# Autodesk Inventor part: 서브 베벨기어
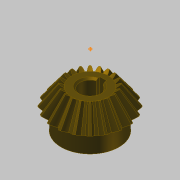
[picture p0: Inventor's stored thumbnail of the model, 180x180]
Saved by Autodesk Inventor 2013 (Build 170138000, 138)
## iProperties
Created: 2014-10
Part Number: 서브 베벨기어
Material: 강철, 탄소
Document SubType Name: Modeling
Designer: KYOUNG IL JANG
Categories: <?xml version="1.0" encoding="UTF-16"?> <MemberInstance><Categories><FamilyTemplate><FamilyTemplateParameter ValueType="xs:double" Id="1" ObjectReferenceKey="da
Mass: 134.866 g
Surface Area: 63.6518 cm^2
Volume: 17.1585 cm^3
Density: 7.86 g/cm^3
CustomPartVersion: 1
Revision Number: 1
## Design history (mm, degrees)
node "맨 위 점"
node "메쉬 평면2"
sketch "톱니 본체 스케치"
  geometry: L1 (0, 0)-(18.003, -31.331); L2 (18.003, -31.331)-(21.664, -28.891); L3 (21.664, -28.891)-(0, 0); L4 (20, -30)-(0, 0); L5 (10.813, -18.818)-(13.012, -17.352); L6 (18.003, -31.331)-(10.813, -18.818); L7 (21.664, -28.891)-(13.012, -17.352); L8 (0, -39.387)-(0, 6.564) reference; L9 (0, -30)-(21.664, -30)
  constraints: 16 end point, 4 point on line, 3 perpendicular, 2 collinear, 1 horizontal alignment, 1 vertical alignment
  dimensions: "d0" = 40 diameter of L4.start L8 (= da_de); "d1" = 36.00616 diameter of L1.end L8 (= da_dfe); "d2" = 43.3282 diameter of L2.end L8 (= da_dae); "d3" = 14.4 distance between parallel lines of L2 L5 (= da_b); "d4" = 28.8906 vertical distance of L2.end L1.start (= da_ve)
revolve "톱니 본체" sketch "톱니 본체 스케치" stored, may be unused: angle "d5" = 90 deg
node "시작점"
node "톱니 평면"
sketch "시작 스케치"
  geometry: L1 (0, -23.505)-(0, 10.645) reference; L2 (-0.834, -2.928)-(0.834, -2.928); A1 r 8.898 centre (-9.698, -3.713) between (-0.834, -2.928) and (-3.903, 3.04); A2 r 8.898 centre (9.698, -3.713) between (3.903, 3.04) and (0.834, -2.928); A3 r 27.357 centre (0, -24.037) between (3.903, 3.04) and (-3.903, 3.04); 1 further point
  constraints: 6 point on circle, 3 centre point, 3 symmetric about line, 2 end point, 1 coincident, 1 perpendicular, 1 other
  dimensions: "d7" = 8.89846 radius of A1 (= fd_rr); "d8" = 9.69794 horizontal distance of point (0, -24.037) A1.centre (= fd_x); "d9" = 20.32439 vertical distance of point (0, -24.037) A1.centre (= fd_y); "d57" = 27.35701 radius of A3 (= 0.5 x fd_dva + 0.3 x da_he); "d58" = 21.10901 distance from line of A3.centre L2 (= 0.5 x fd_dva - 1.12 x da_he)
node "끝점"
  node "끝 평면"
sketch "3D 스케치 오른쪽"
  node "Helical Curve Right" dims "d65" = 229.90621 (computed from da_dm, da_delta, da_beta), "d66" = 31.5, "d67" = 40 (= da_de), "d68" = -5.88003 (= -da_delta), "d69" = 12.16458 (computed from fd_loft, da_delta)
node "끝 평면 오른쪽"
sketch "끝 스케치 오른쪽"
  geometry: L1 (0, -22.649)-(0, 12.15) reference; L2 (-0.497, -1.72)-(0.497, -1.72); A1 r 5.299 centre (-5.775, -2.187) between (-0.497, -1.72) and (-2.324, 1.834); A2 r 5.299 centre (5.775, -2.187) between (2.324, 1.834) and (0.497, -1.72); A3 r 16.291 centre (0, -14.29) between (2.324, 1.834) and (-2.324, 1.834); 1 further point
  constraints: 6 point on circle, 3 centre point, 3 symmetric about line, 2 end point, 1 coincident, 1 perpendicular, 1 other
  dimensions: "d70" = 5.77526 horizontal distance of A3.centre A1.centre (computed from fd_x, fd_ratio); "d71" = 12.10346 vertical distance of point (0, -14.29) A1.centre (computed from fd_y, fd_ratio); "d72" = 5.29916 radius of A1 (computed from fd_rr, fd_ratio); "d73" = 12.57071 distance from line of point (0, -14.29) L2 (computed from d58, fd_ratio); "d74" = 16.29149 radius of A3 (computed from d57, fd_ratio)
feature "로프트 오른쪽" sketch "끝 스케치 오른쪽" dims "d75" = 0, "d77" = 0, "d79" = 0, "d80" = 90 deg, "d85" = 20, "d92" = 90 deg, "d93" = 90 deg, "da_teethtype" = 0 [user parameter]
sketch "3D 스케치 왼쪽"
  node "Helical Curve Left" dims "d26" = 229.90621 (computed from da_dm, da_delta, da_beta), "d27" = 12.16458 (computed from fd_loft, da_delta), "d28" = 40 (= da_de), "d29" = -5.88003 (= -da_delta)
node "끝 평면 왼쪽"
sketch "끝 스케치 왼쪽" dims "d56" = 10.82768 (derived)
  geometry: L1 (0, -35.087)-(0, 18.089) reference; L2 (-0.497, -1.716)-(0.497, -1.716); A1 r 5.299 centre (-5.775, -2.183) between (-0.497, -1.716) and (-2.324, 1.838); A2 r 5.299 centre (5.775, -2.183) between (2.324, 1.838) and (0.497, -1.716); A3 r 16.291 centre (0, -14.287) between (2.324, 1.838) and (-2.324, 1.838); 2 further points; 1 other entity
  constraints: 6 point on circle, 3 centre point, 3 symmetric about line, 2 end point, 1 coincident, 2 other
  dimensions: "d30" = 5.29916 radius of A1 (computed from fd_rr, fd_ratio); "d31" = 5.77526 horizontal distance of point (0, -14.287) A1.centre (computed from fd_x, fd_ratio); "d32" = 12.10346 vertical distance of A1.centre point (0, -14.287) (computed from fd_y, fd_ratio); "d61" = 16.29149 radius of A3 (computed from d57, fd_ratio); "d62" = 12.57071 distance from line of point (0, -14.287) L2 (computed from d58, fd_ratio)
feature "로프트 왼쪽" sketch "끝 스케치 왼쪽" dims "d35" = 0, "d37" = 0, "d39" = 0, "d40" = 90 deg, "d84" = 10, "d90" = 90 deg, "d91" = 90 deg, "da_teethtype" = 0 [user parameter]
sketch "본체 스케치"
  geometry: L1 (0, -35.038)-(0, -19.531) reference; L2 (18.003, -31.331)-(10.813, -18.818) reference; L3 (10.813, -18.818)-(0, -18.818); L4 (18.003, -31.331)-(0, -31.331)
  constraints: 4 end point, 2 perpendicular, 2 point on line
revolve "본체 고정" sketch "본체 스케치" stored, may be unused: angle "d46" = 90 deg
feature "피치 지름" dims angle "d47" = 90 deg
sketch "스케치8"
  geometry: C1 r 17 at (0, 0); 1 further point
  constraints: 1 centre point, 1 coincident
  dimensions: "d94" = 34 diameter of C1
extrude "돌출1" join sketch "스케치8" distance "d95" = 10; taper "d96" = 0 deg
sketch "스케치9"
  geometry: 1 further point
hole "구멍1" sketch "스케치9" at (0, 0) diameter "d97" = 12; stored, may be unused: countersink angle "d101" = 90 deg, drill point angle "d103" = 118 deg; dims "d98" = 6, "d99" = 4, "d100" = 2, "d102" = 8
sketch "스케치10"
  geometry: 1 further point
sketch "스케치11"
  geometry: 1 further point
sketch "스케치12"
  geometry: L1 (-2, 5.657)-(-2, 7.8); L2 (-2, 7.8)-(2, 7.8); L3 (2, 7.8)-(2, 5.657); A1 r 6 centre (0, 0) between (-2, 5.657) and (2, 5.657) reference; 1 further point
  constraints: 6 end point, 2 parallel, 2 point on circle, 1 perpendicular, 1 vertical
  dimensions: "d104" = 4 distance of L1.end L2.end; "d105" = 13.8 dimension on A1 L2
extrude "돌출2" cut sketch "스케치12" stored distance "d106" = 7; taper "d107" = 0 deg
chamfer "모따기1" distance "d108" = 1; stored, may be unused: second distance "d109" = 2, angle "d110" = 45 deg
body "Solid1"
feature "로프트" dims "d17" = 0, "d18" = 90 deg, "d19" = 0, "d20" = 90 deg, "d89" = 0, "da_teethtype" = 0 [user parameter]
pattern_circular "원형 패턴" dims angle "d22" = 360 deg, "d88" = 0, "da_teethtype" = 0 [user parameter]
pattern_circular "원형 패턴 오른쪽" dims angle "d82" = 360 deg, "da_teethtype" = 0 [user parameter]
pattern_circular "원형 패턴 왼쪽" dims angle "d42" = 360 deg, "da_teethtype" = 0 [user parameter]
sketch "끝 스케치"
  geometry: L1 (0, -15.359)-(0, 6.983) reference; L2 (-0.497, -1.72)-(0.497, -1.72); A1 r 5.299 centre (-5.775, -2.187) between (-0.497, -1.72) and (-2.324, 1.834); A2 r 5.299 centre (5.775, -2.187) between (2.324, 1.834) and (0.497, -1.72); A3 r 16.291 centre (0, -14.29) between (2.324, 1.834) and (-2.324, 1.834); 1 further point
  constraints: 6 point on circle, 3 centre point, 3 symmetric about line, 2 end point, 1 coincident, 1 other
  dimensions: "d12" = 5.29916 radius of A1 (computed from fd_rr, fd_ratio); "d15" = 5.77526 horizontal distance of A1.centre point (0, -14.29) (computed from fd_x, fd_ratio); "d16" = 12.10346 vertical distance of A1.centre point (0, -14.29) (computed from fd_y, fd_ratio); "d59" = 16.29149 radius of A3 (computed from d57, fd_ratio); "d60" = 12.57071 distance from line of A3.centre L2 (computed from d58, fd_ratio)
sketch "Sketch6"
  geometry: L1 (20, -30)-(0, 0) reference; L2 (0, -37.8)-(0, 6.3) reference
body "Srf1"
other parameters: "da_b" = 14.4 [user parameter; used in 2 equation terms], "da_de" = 40 [user parameter; used in 4 equation terms], "da_dae" = 43.3282 [user parameter; used in 2 equation terms], "da_dfe" = 36.00616 [user parameter; used in 1 equation term], "da_le" = 36.05551 [user parameter; used in 1 equation term], "da_omega" = 90 deg [user parameter; used in 1 equation term], "da_beta" = 0 [user parameter; used in 2 equation terms], "da_delta" = 5.88003 [user parameter; used in 8 equation terms], "da_alpha" = 20 deg [user parameter; used in 2 equation terms], "da_he" = 4.4 [user parameter; used in 4 equation terms], "da_ve" = 28.8906 [user parameter; used in 1 equation term], "fd_dv" = 48.07402 (computed from da_de, da_delta) [user parameter; used in 1 equation term], "fd_dva" = 52.07402 (computed from da_dae, da_delta) [user parameter; used in 3 equation terms], "fd_dvb" = 45.1748 (computed from fd_dv, da_alpha) [user parameter; used in 2 equation terms], "da_zv" = 240.37008 [user parameter; used in 1 equation term], "fd_loft" = 14.62 (= da_b + 0.05 x da_he) [user parameter; used in 4 equation terms], "fd_ratio" = 5.95514 (computed from da_le, fd_loft) [user parameter; used in 15 equation terms], "fd_rr" = 8.89846 (computed from fd_dd, fd_dvb) [user parameter; used in 6 equation terms], "fd_angle" = 0.66075 (computed from da_zv) [user parameter; used in 4 equation terms], "fd_x1" = 1.58709 (computed from da_dvw, fd_angle) [user parameter; used in 1 equation term], "fd_y1" = 23.98456 (computed from da_dvw, fd_angle) [user parameter; used in 1 equation term], "fd_x2" = 8.11084 (computed from fd_rr, fd_angle2, fd_angle) [user parameter; used in 1 equation term], "fd_y2" = 3.66016 (computed from fd_rr, fd_angle2, fd_angle) [user parameter; used in 1 equation term], "fd_x" = 9.69794 (= fd_x1 + fd_x2) [user parameter; used in 4 equation terms], "fd_y" = 20.32439 (= fd_y1 - fd_y2) [user parameter; used in 4 equation terms], "fd_angle2" = 3.57832 (computed from fd_dvb, fd_dd, da_alpha) [user parameter; used in 2 equation terms], "fd_dd" = 48.55402 (= fd_dva - 0.8 x da_he) [user parameter; used in 2 equation terms], "da_dvw" = 48.07402 [user parameter; used in 2 equation terms], "d11" = 14.62 (= fd_loft), "da_dm" = 32.01232 [user parameter; used in 2 equation terms], "da_x" = 0 [user parameter], "da_m" = 2 [user parameter], "d48" = 0, "d49" = 0, "d50" = 90 deg (= da_omega), "d51" = 9 deg (computed from da_z), "d52" = 0, "d53" = 0, "d54" = 0
